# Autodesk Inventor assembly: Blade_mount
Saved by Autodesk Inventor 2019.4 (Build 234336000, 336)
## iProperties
Created: 2020-04
Part Number: Blade_mount
Document SubType Name: Assembly
Designer: Administrator
Title: Blade_mount v18
Author: Administrator
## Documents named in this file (10)
- c:\worker\convert-fusion-r03\tmp\job-1\48\output\files\ccae6ef3-9f0e-42ff-b199-3a2c6474057a\Blade_mount v18_2.iam
- c:\worker\convert-fusion-r03\tmp\job-1\48\output\files\ccae6ef3-9f0e-42ff-b199-3a2c6474057a\Component1.ipt
- c:\worker\convert-fusion-r03\tmp\job-1\48\output\files\ccae6ef3-9f0e-42ff-b199-3a2c6474057a\Component2.ipt
- c:\worker\convert-fusion-r03\tmp\job-1\48\output\files\ccae6ef3-9f0e-42ff-b199-3a2c6474057a\Component3.ipt
- c:\worker\convert-fusion-r03\tmp\job-1\48\output\files\ccae6ef3-9f0e-42ff-b199-3a2c6474057a\Component4.ipt
- c:\worker\convert-fusion-r03\tmp\job-1\48\output\files\ccae6ef3-9f0e-42ff-b199-3a2c6474057a\Component5.ipt
- c:\worker\convert-fusion-r03\tmp\job-1\48\output\files\ccae6ef3-9f0e-42ff-b199-3a2c6474057a\Component6.ipt
- c:\worker\convert-fusion-r03\tmp\job-1\48\output\files\ccae6ef3-9f0e-42ff-b199-3a2c6474057a\Component7.ipt
- c:\worker\convert-fusion-r03\tmp\job-1\48\output\files\ccae6ef3-9f0e-42ff-b199-3a2c6474057a\Component8.ipt
- c:\worker\convert-fusion-r03\tmp\job-1\48\output\files\ccae6ef3-9f0e-42ff-b199-3a2c6474057a\Component9.ipt
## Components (9 placed, 9 different names)
1. Component1:1
2. Component2:1
3. Component3:1
4. Component4:1
5. Component5:1
6. Component6:1
7. Component7:1
8. Component8:1
9. Component9:1
